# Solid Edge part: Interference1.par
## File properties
Author: Deepak Maini
Last saved by: Robert a Rhodes jr
Revision: 41
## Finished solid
Body 1: solid body, 5 faces, 5 edges, 0 vertices.
  Faces by surface: plane 3, cylinder 2
  Edges by curve: circle 5
Bounding box of the edges (mm): 16.000 x 16.000 x 24.000, from (-8, 10.936, 154) to (8, 26.936, 178).
Cylindrical faces by radius (mm): R6.5 x1, R8 x1
Planar faces by outward normal: +z 2, -z 1
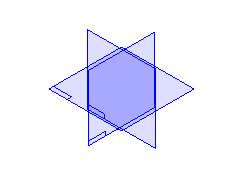
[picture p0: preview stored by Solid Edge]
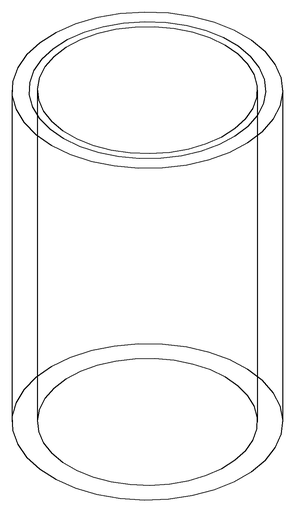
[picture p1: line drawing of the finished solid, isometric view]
